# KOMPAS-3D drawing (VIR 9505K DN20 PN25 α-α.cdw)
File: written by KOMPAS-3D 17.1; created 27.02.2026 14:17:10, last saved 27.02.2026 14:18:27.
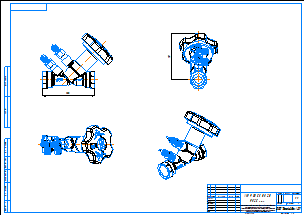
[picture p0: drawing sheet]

Sheet 1: A2, landscape

Title block, sheet 1: name: VIR 9505K DN20 / PN25 р-р; material: Внимание! Данный продукт является объектом авторского права ООО «Торговый Дом АДЛ». / Запрещается изменение, копирование, распространение / (в том числе путем копирования на другие сайты и ресурсы в Интернете) / или любое иное использование информации и объектов без предварительного / согласия правообладателя (ООО «Торговый Дом АДЛ»).; sheets: 1; organisation: ООО "Торговый дом АДЛ"; sheet format: A2

Views: Вид 1, Спереди, Проекционный вид 2, Проекционный вид 3, Вид 4, Изометрия
Referenced files in C:\Users\mipv\Desktop\VIR 9505K STP формат\: VIR 9505K DN20 PN25 р-р.m3d
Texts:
  adm
Dimensions and other numbers on the sheet: 90; 102; 1:1; 1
